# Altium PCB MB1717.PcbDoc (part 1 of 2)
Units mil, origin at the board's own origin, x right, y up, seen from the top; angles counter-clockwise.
Board outline 2760.94 x 3253.06 mil, 2 copper layers (Top Layer, Bottom Layer), stack 60.756 mil thick; 141 components, 128 nets, 519 pads, 417 vias.
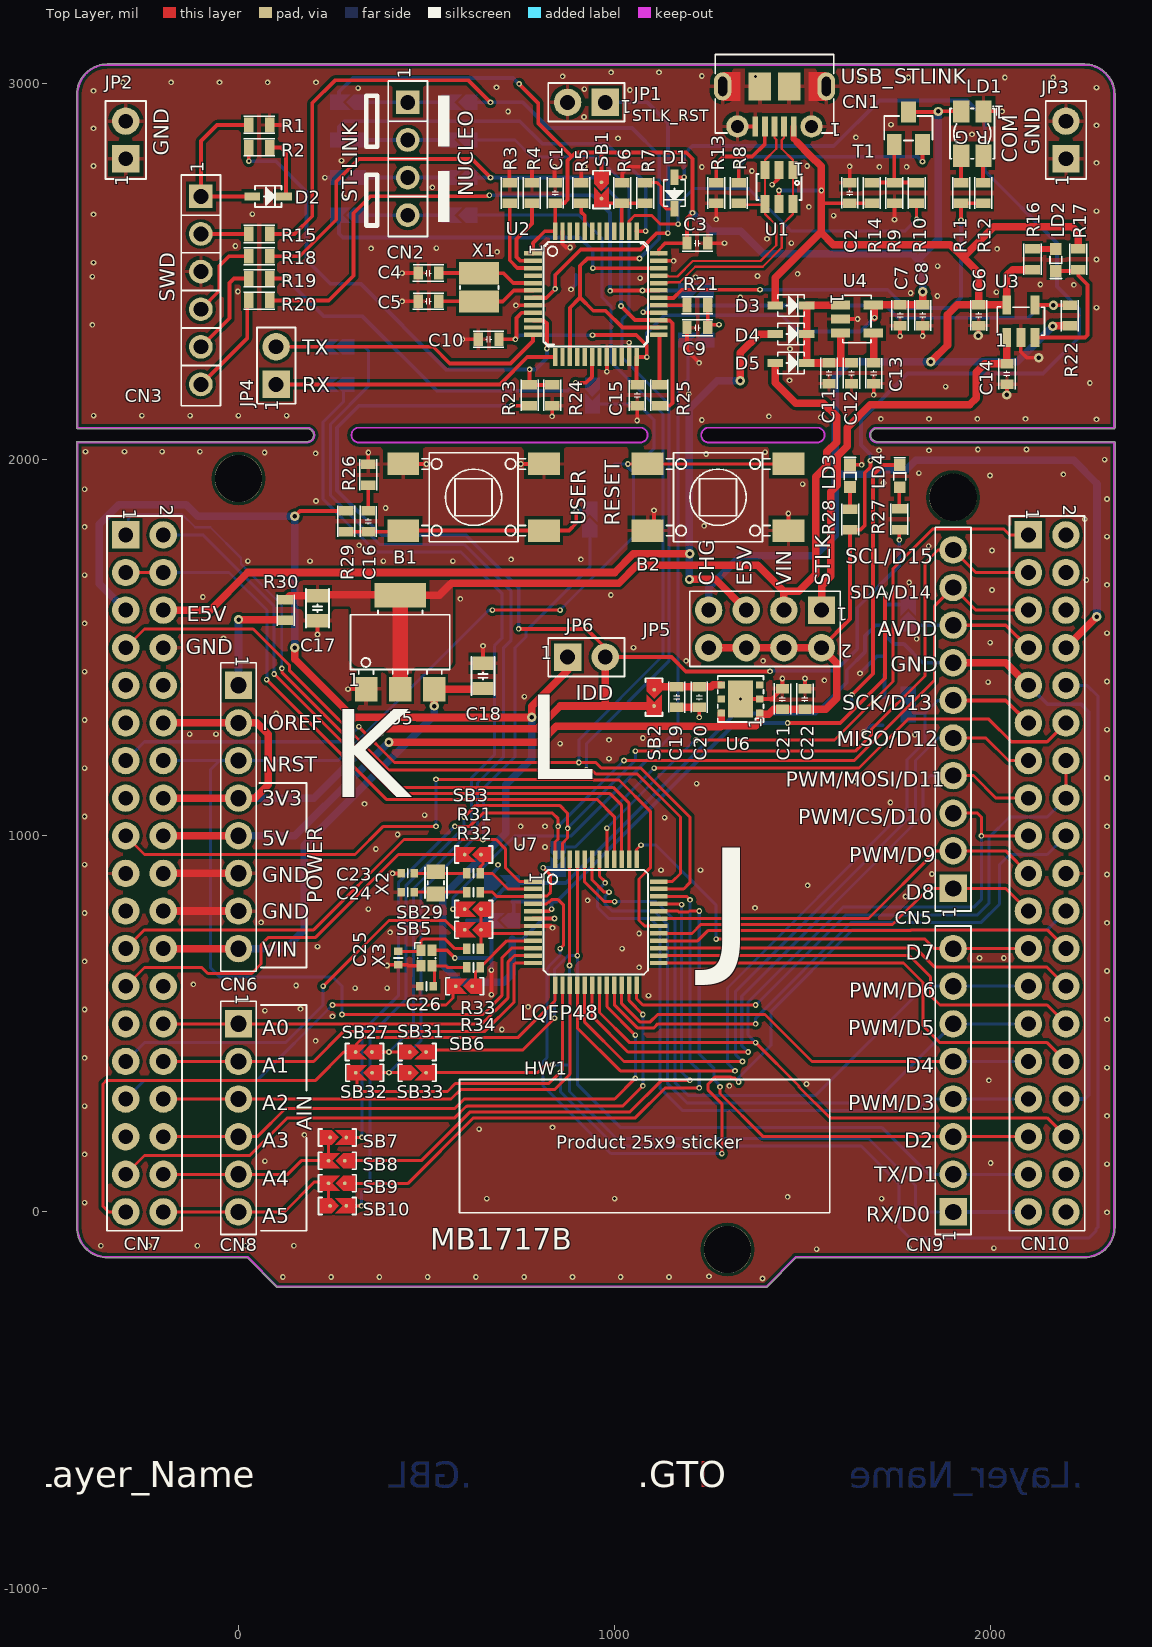
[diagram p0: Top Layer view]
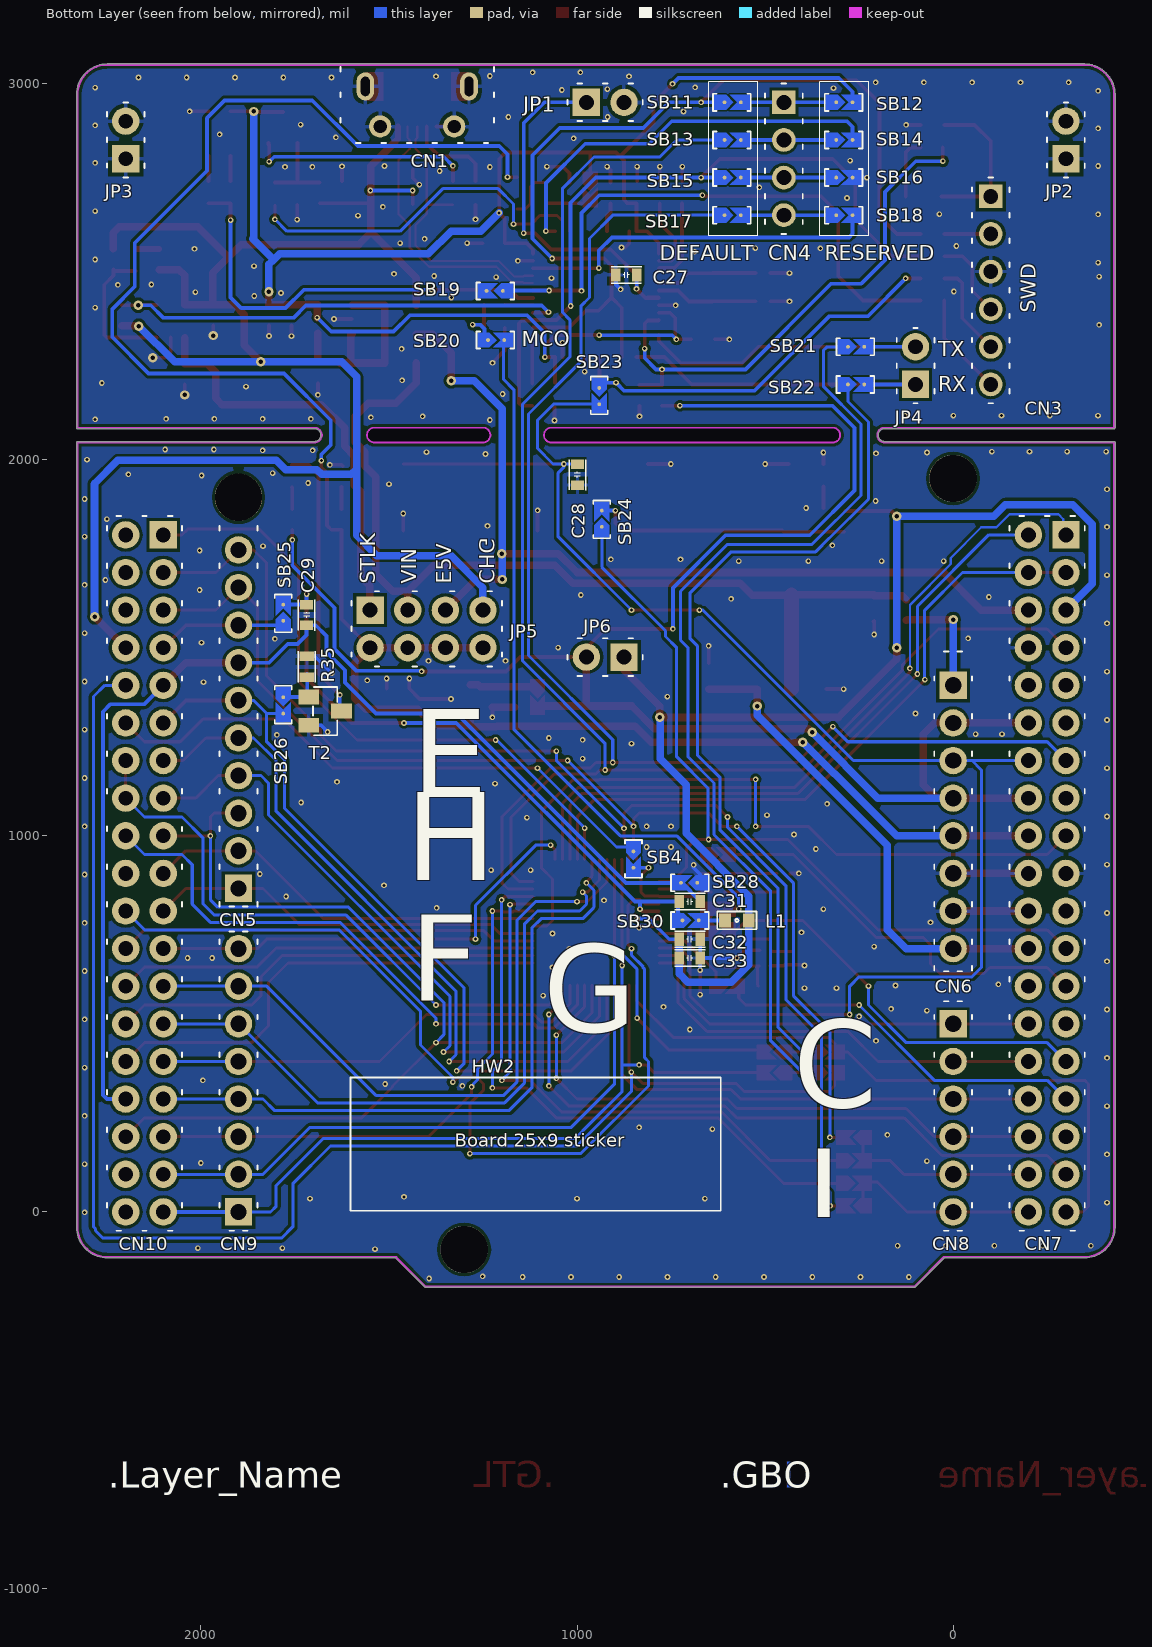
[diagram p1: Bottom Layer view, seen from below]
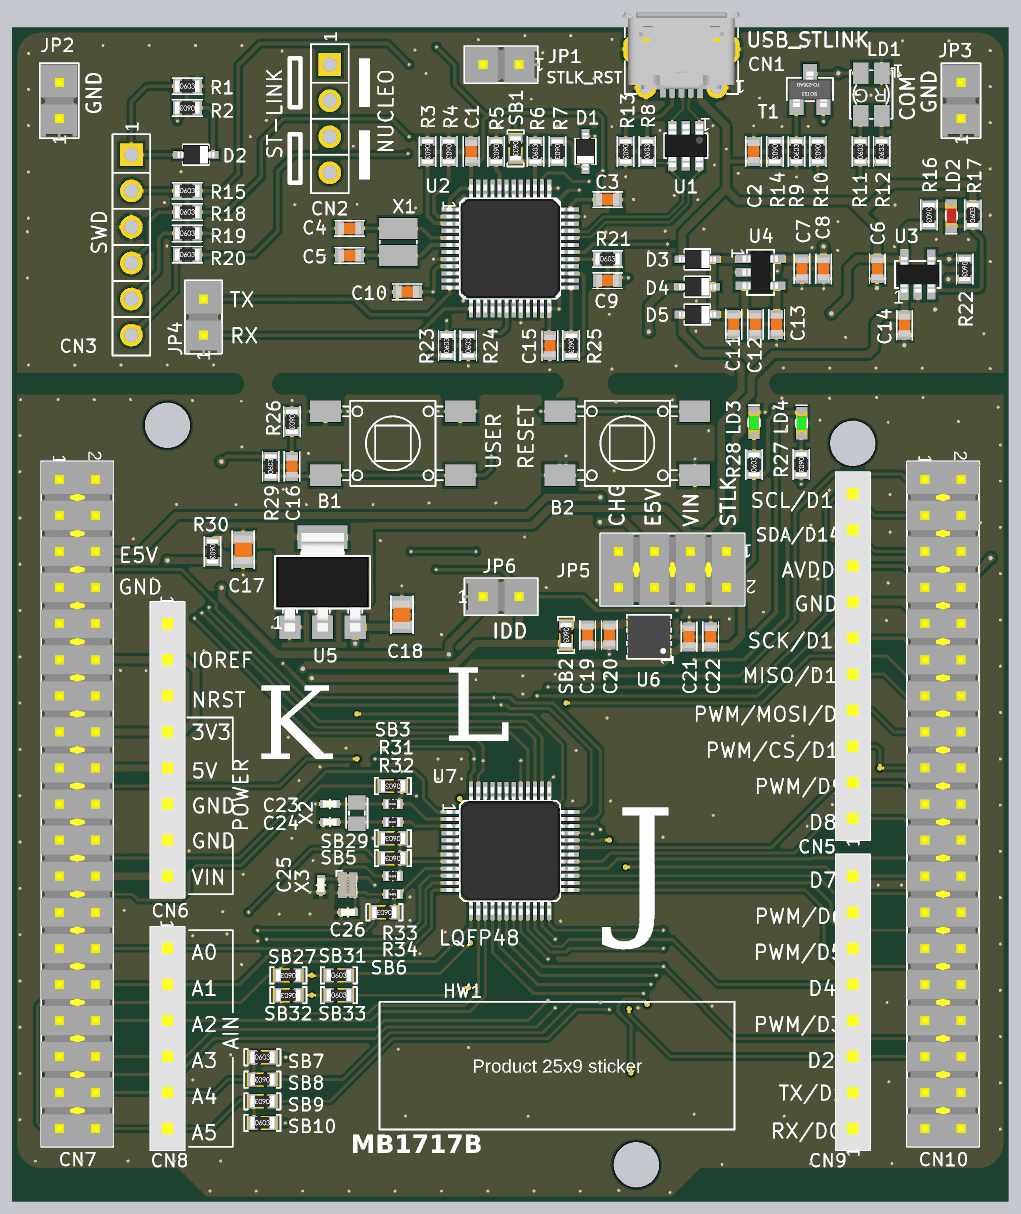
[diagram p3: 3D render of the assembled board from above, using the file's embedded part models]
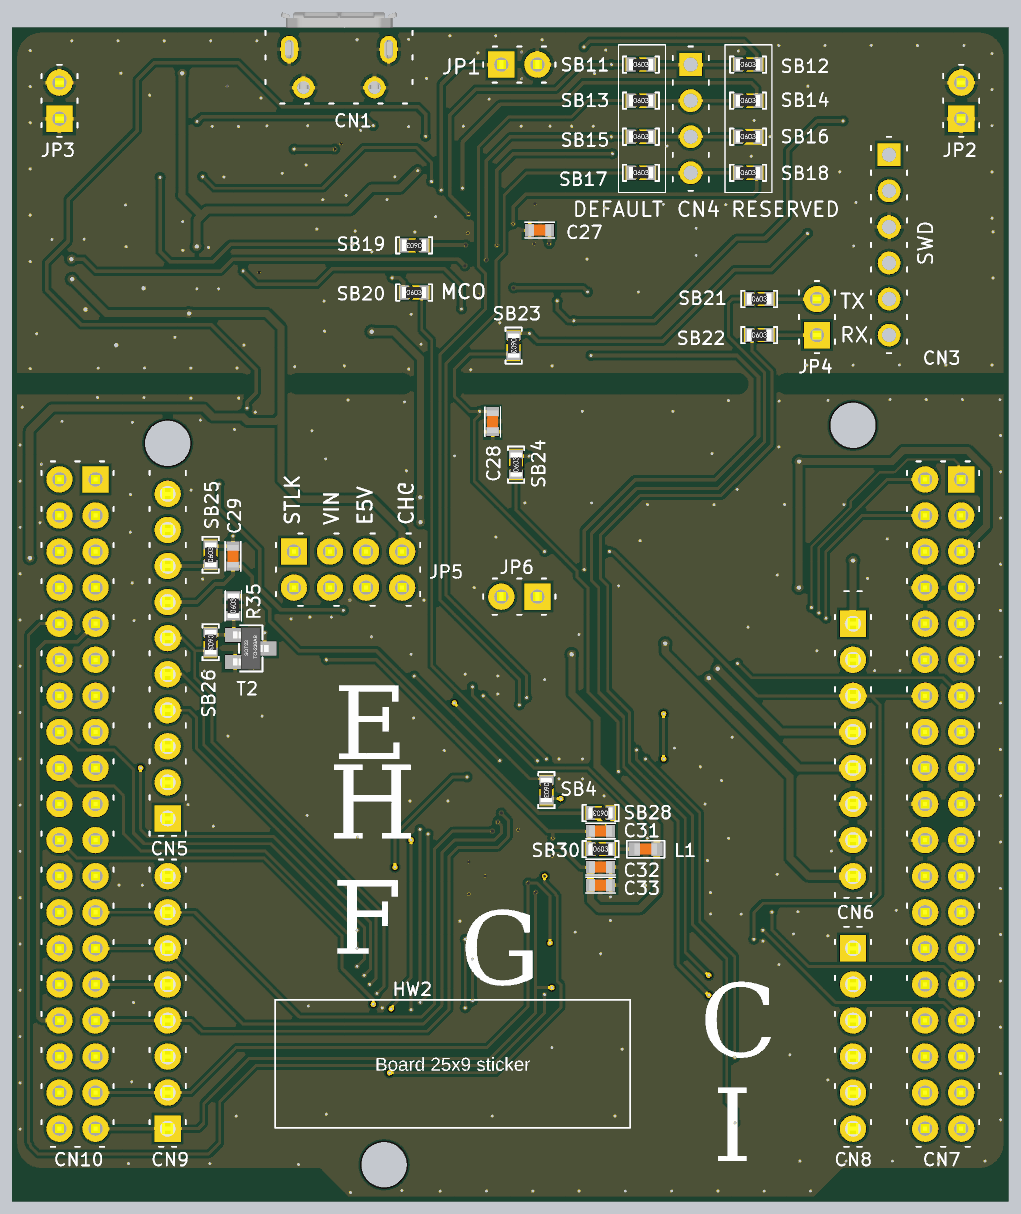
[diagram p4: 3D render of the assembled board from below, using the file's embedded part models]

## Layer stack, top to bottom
Top Solder: solder mask 0.591, Solder Resist, Dk 3.5
Top Layer: signal copper 1.378
Dielectric 1: core 58, FR-4, Dk 4.2
Bottom Layer: signal copper 1.378
Bottom Solder: solder mask 0.591, Solder Resist, Dk 3.5

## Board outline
-430.46,-40.95 ccw(c-349.21,-40.95) -349.21,-122.2 ccw(c-349.21,-119.69) -349.17,-122.2 23.77,-122.2 101.77,-200.2 ccw(c103.55,-198.43) 103.55,-200.94 1402.76,-200.94 ccw(c1402.76,-198.43) 1404.54,-200.2 1404.55,-200.19 cw(c1402.76,-198.43) 1404.53,-200.21 1482.54,-122.2 2249.22,-122.2 ccw(c2249.22,-40.95) 2330.47,-40.95 2330.47,2045.67 ccw(c2327.96,2045.67) 2327.96,2048.18 1698.04,2048.18 cw(c1698.04,2065.35) 1698.04,2082.52 2327.93,2082.52 ccw(c2327.96,2085.04) 2330.47,2085.04 2330.47,2970.87 ccw(c2249.22,2970.87) 2249.24,3052.12 ccw(c2249.22,3049.61) 2249.22,3052.12 -349.21,3052.12 ccw(c-349.21,3049.61) -349.23,3052.12 cw(c-349.21,2970.87) -349.21,3052.12 -349.23,3052.12 ccw(c-349.21,2970.87) -430.46,2970.87 -430.46,2085.04 ccw(c-427.95,2085.04) -427.92,2082.52 182.29,2082.52 cw(c182.29,2065.35) 199.46,2065.35 cw(c182.29,2065.35) 182.29,2048.18 -427.95,2048.18 ccw(c-427.95,2045.67) -430.46,2045.65
cut-out: 1250,2045.67 1538.59,2045.67 ccw(c1538.59,2065.35) 1538.59,2085.04 1250,2085.04 ccw(c1250,2065.35)
cut-out: 320.08,2045.67 1068.11,2045.67 ccw(c1068.11,2065.35) 1068.11,2085.04 320.08,2085.04 ccw(c320.08,2065.35)

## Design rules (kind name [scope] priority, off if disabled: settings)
Clearance U6 [(HasFootprint('ICC_DFN6-EPAD_3X3_P095'))] p1: gap=7 ignorepadtopadclearanceinfootprint=FALSE
Clearance X3 [(HasFootprint('CRY_NX1612SA_4P'))] p2: gap=5 ignorepadtopadclearanceinfootprint=FALSE
Clearance SB [(HasFootprint('SOLDER-BRIDGE_R0603-0R'))] p3: gap=5 ignorepadtopadclearanceinfootprint=FALSE except(0: Arc-Hole Track-Hole SMDPad-Hole THPad-Hole Via-Hole Fill-Hole Poly-Hole Region-Hole Text-Hole)
Clearance U2 [(ObjectKind = 'Pad') And (Component = 'U2') vs (ObjectKind = 'Pad') And (Component = 'U2')] p4: gap=7.8 ignorepadtopadclearanceinfootprint=FALSE except(0: Arc-Hole Track-Hole SMDPad-Hole THPad-Hole Via-Hole Fill-Hole Poly-Hole Region-Hole Text-Hole)
Clearance U7 [(ObjectKind = 'Pad') And (Component = 'U7') vs (ObjectKind = 'Pad') And (Component = 'U7')] p5: gap=7.8 ignorepadtopadclearanceinfootprint=FALSE except(0: Arc-Hole Track-Hole SMDPad-Hole THPad-Hole Via-Hole Fill-Hole Poly-Hole Region-Hole Text-Hole)
Clearance [All] p6: gap=8 ignorepadtopadclearanceinfootprint=FALSE except(0: Arc-Hole Track-Hole SMDPad-Hole THPad-Hole Via-Hole Fill-Hole Poly-Hole Region-Hole Text-Hole)
ComponentClearance [All] p1: gap=7.87 collisioncheckmode=3 verticalgap=7.87 showdistances=FALSE
DiffPairsRouting [All] p1: maxlimit=8.9 minlimit=8.9 mostfreqgap=8.9 toplayer_minwidth=15 toplayer_maxwidth=15 toplayer_prefwidth=15 bottomlayer_minwidth=15 bottomlayer_maxwidth=15 bottomlayer_prefwidth=15 maxuncoupledlength=500
HoleSize [All] p1: absolutevalues=TRUE maxlimit=150 minlimit=1 maxpercent=80.000 minpercent=20.000
MinimumSolderMaskSliver [All] p1: minsoldermaskwidth=0
PolygonConnect VIA [IsVia] p1: connectstyle=Direct reliefconductorwidth=10 reliefentries=4 polygonreliefangle="90 Angle" airgapwidth=10
PolygonConnect [All] p2: connectstyle=Relief reliefconductorwidth=10 reliefentries=4 polygonreliefangle="90 Angle" airgapwidth=10
RoutingVias [All] p1: holewidth=12 width=20 viastyle="Through Hole" minholewidth=8 minwidth=15 maxholewidth=28 maxwidth=50
SilkToSilkClearance [All] p1: silktosilkclearance=4
SilkToSolderMaskClearance [IsPad] p1: minsilkscreentomaskgap=0.5 clearancetoexposedcopper=TRUE
SolderMaskExpansion [All] p1: expansion=4 istentingtop=FALSE
Width [All] p1: maxlimit=40 minlimit=6 preferedwidth=10 minimp=50.000000 maximp=50.000000 favimp=50.000000
24 further rules are at their usual default settings.

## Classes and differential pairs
net class PF[0..3]: PF0 PF1 PF2 PF3
net class PD[0..3]: PD0 PD1 PD2 PD3
net class PC[6..15]: PC6 PC7 PC13 PC14 PC15
net class PB[0..15]: PB0 PB1 PB2 PB3 PB4 PB5 PB6 PB7 PB8 PB9 PB10 PB11 PB12 PB13 PB14 PB15
net class PA[0..15]: PA0 PA1 PA2 PA3 PA4 PA5 PA6 PA7 PA8 PA9 PA10 PA11 PA12 PA13 PA14 PA15
component class U_Arduino_Morpho_connectors: C29 CN5 CN6 CN7 CN8 CN9 CN10 LD4 R27 R30 R35 SB3 SB4 SB5 SB6 SB7 SB8 SB9 SB10 SB25 SB26 T2
component class ST_LINK_V2-1: C1 C2 C3 C4 C5 C6 C7 C8 C9 C10 C11 C12 C13 C14 C15 C27 CN1 CN2 CN3 D1 D2 D3 D4 D5 HW6 HW7 HW8 HW9 JP1 JP2 JP3 JP4 LD1 LD2 R1 R2 R3 R4 R5 R6 R7 R8 R9 R10 R11 R12 R13 R14 R15 R16 R17 R18 R19 R20 R21 R22 R23 R24 R25 SB1 SB11 SB12 SB13 SB14 SB15 SB16 SB17 SB18 SB19 SB20 SB21 SB22 SB23 T1 U1 U2 U3 U4 X1
component class Power: C17 C18 C19 C20 C21 C22 HW12 HW13 JP5 JP6 LD3 R28 SB2 U5 U6
component class MCU: B1 B2 C16 C23 C24 C25 C26 C28 C31 C32 C33 HW10 HW11 L1 R26 R29 R31 R32 R33 R34 SB24 SB27 SB28 SB29 SB30 SB31 SB32 SB33 U7 X2 X3
component class HW_Mechanical_Parts: HW1 HW2 HW4
differential pair STL_USB_D: +STL_USB_D_P -STL_USB_D_N

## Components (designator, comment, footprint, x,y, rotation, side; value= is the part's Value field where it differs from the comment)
B1 "SW-PUSH-CMS" SWI_WEALTHMETAL_TD-0341_4P_BLUE 625,1900 r270 top locked value=SWITCH
B2 "SW-PUSH-CMS" SWI_WEALTHMETAL_TD-0341_4P_BLACK 1275,1900 r90 top locked value=SWITCH
C1 "Capacitor" C0603 842,2709 r270 top value=100nF
C2 "Capacitor" C0603 1625,2709 r270 top value=100nF
C3 "Capacitor" C0603 1220,2575.68 r180 top value=100nF
C4 "Capacitor" C0603 505,2496 r0 top value=10pF
C5 "Capacitor" C0603 505,2421 r0 top value=10pF
C6 "Capacitor" C0603 1968,2384 r90 top value=1uF
C7 "Capacitor" C0603 1759.02,2383.94 r90 top value=1uF
C8 "Capacitor" C0603 1819.02,2383.94 r90 top value=100nF
C9 "Capacitor" C0603 1220,2351 r180 top value=20pF
C10 "Capacitor" C0603 665,2320 r0 top value=100nF
C11 "Capacitor" C0603 1569.87,2230 r90 top value=100nF
C12 "Capacitor" C0603 1629.87,2230 r90 top value=1uF
C13 "Capacitor" C0603 1688.87,2229.94 r90 top value=10nF
C14 "Capacitor" C0603 2043,2228 r90 top value=100nF
C15 "Capacitor" C0603 1060,2171 r90 top value=100nF
C16 "Capacitor" C0603 345,1836 r270 top value=100nF
C17 "Capacitor" C0805 210,1605 r90 top value=10uF
C18 "Capacitor" C0805 650,1425 r270 top value=10uF
C19 "Capacitor" C0603 1165,1368.69 r90 top value=100nF
C20 "Capacitor" C0603 1225,1368.69 r90 top value=1uF
C21 "Capacitor" C0603 1446,1363.69 r270 top value=100nF
C22 "Capacitor" C0603 1506,1363.69 r270 top value=1uF
C23 "Capacitor" C0402 450,900 r0 top value=8.2pF
C24 "Capacitor" C0402 450,850 r0 top value=8.2pF
C25 "Capacitor" C0402 425,675 r90 top value=4.3pF
C26 "Capacitor" C0402 500,600 r0 top value=4.3pF
C27 "Capacitor" C0603 869,2491 r0 bottom value=100nF
C28 "Capacitor" C0603 999,1959.97 r90 bottom value=100nF
C29 "Capacitor" C0603 1719,1587.06 r90 bottom value=100nF
C31 "Capacitor" C0603 700,825 r0 bottom value=100nF
C32 "Capacitor" C0603 700,725 r0 bottom value=100nF
C33 "Capacitor" C0603 700,675 r0 bottom value=4.7uF
CN1 "USB_uB_105017.0001" CON_USBMICROB_MOLEX_105017-0001_H2P90 1425,3049.39 r180 top locked value=USB_uB_105017-0001
CN2 "Header 4x1" CON_988-JIUBABA_PHFS25-11-04-G0B115-T-1 450,2800 r90 top
CN3 "Header 6x1" CON_988-JIUBABA_PHFS25-11-06-G0B115-T-1 -100,2450 r90 top locked value="Header 1x6"
CN5 "Socket 10x1" CON_SAMTEC_SSW-110-03-X-S 1900,1310 r90 top locked
CN6 "Socket 8x1" CON_SAMTEC_SSW-108-03-X-S 0,1050 r270 top locked
CN7 "Header 19x2" CON_SAMTEC_TSW-119-09-X-D -250,900 r270 top locked
CN8 "Socket 6x1" CON_SAMTEC_SSW-106-03-X-S 0,250 r270 top
CN9 "Socket 8x1" CON_SAMTEC_SSW-108-03-X-S 1900,350 r90 top locked
CN10 "Header 19x2" CON_SAMTEC_TSW-119-09-X-D 2150,900 r270 top locked
D1 "BAT60JFILM" DIO_SOD323 1159,2709 r270 top
D2 "BAT60JFILM" DIO_SOD323 79,2700 r0 top
D3 "BAT60JFILM" DIO_SOD323 1469,2410 r0 top locked
D4 "BAT60JFILM" DIO_SOD323 1469,2334 r0 top
D5 "BAT60JFILM" DIO_SOD323 1469,2257 r0 top
HW1 "STICKER_PRODUCT" STICKER_PRODUCT_25X9 1080,175 r0 top value="Sticker product"
HW2 "STICKER_BOARD" STICKER_BOARD_25X9 1110,180 r180 bottom value="Sticker board"
JP1 "Jumper_Header 2x1" CON_SAMTEC_TSW-102-07-G-S 925,2950 r180 top value="Shunt not fitted"
JP2 "Jumper_Header 2x1" CON_SAMTEC_TSW-102-09-X-S -300,2850 r90 top locked value="Header 2x1 16mm"
JP3 "Jumper_Header 2x1" CON_SAMTEC_TSW-102-09-X-S 2200,2850 r90 top locked value="Header 2x1 16mm"
JP4 "Jumper_Header 2x1" CON_SAMTEC_TSW-102-07-G-S 100,2250 r90 top locked value="Shunt not fitted"
JP5 "Jumper_Header 4x2 Fitted 1-2" CON_SAMTEC_TSW-104-07-X-D 1400,1550 r180 top value="Shunt Fitted 1-2"
JP6 "Jumper_Header 2x1 Fitted" CON_SAMTEC_TSW-102-07-G-S 925,1475 r0 top value="Shunt Fitted"
L1 "BEAD" L0603 575,775 r180 bottom value=600R@100MHz
LD1 "LD_BICOLOR_CMS" LED_BI-GR_HSMF-A201-A00J1 1951,2867 r180 top locked
LD2 "LED_red" LED_0603_RED 2173,2531 r270 top value=RED
LD3 "LED_green" LED_0603_GREEN 1626,1956.7 r90 top value=GREEN
LD4 "LED_green" LED_0603_GREEN 1758,1956 r90 top value=GREEN
R1 "Resistor" R0603 55,2890 r0 top value=10K
R2 "Resistor" R0603 55,2830 r180 top value=22R
R3 "Resistor" R0603 721,2709 r270 top value=10K
R4 "Resistor" R0603 780,2709 r270 top value=10K
R5 "Resistor" R0603 911,2709 r270 top value=100K
R6 "Resistor" R0603 1020,2709 r90 top value=4K7
R7 "Resistor" R0603 1081,2709 r270 top value=2K7
R8 "Resistor" R0603 1330,2709 r90 top value=1K5
R9 "Resistor" R0603 1744,2709 r90 top value=36K
R10 "Resistor" R0603 1803,2709 r270 top value=100R
R11 "Resistor" R0603 1921,2709 r90 top value=330R
R12 "Resistor" R0603 1980,2709 r90 top value=330R
R13 "Resistor" R0603 1270,2709 r270 top value=100K
R14 "Resistor" R0603 1684,2709 r270 top value=10K
R15 "Resistor" R0603 55,2600 r0 top value=22R
R16 "Resistor" R0603 2111,2533 r270 top value=1K
R17 "Resistor" R0603 2232.64,2533 r90 top value=47K
R18 "Resistor" R0603 55,2541 r0 top value=22R
R19 "Resistor" R0603 55,2482 r0 top value=22R
R20 "Resistor" R0603 55,2423 r0 top value=22R
R21 "Resistor" R0603 1220,2411 r0 top value=100R
R22 "Resistor" R0603 2210,2383 r270 top value=47K
R23 "Resistor" R0603 774,2171 r90 top value=4K7
R24 "Resistor" R0603 834,2171 r90 top value=4K7
R25 "Resistor" R0603 1119,2171 r270 top value=100R
R26 "Resistor" R0603 345,1960 r270 top value=100R
R27 "Resistor" R0603 1757,1841.3 r270 top value=510R
R28 "Resistor" R0603 1626,1841 r90 top value=1K
R29 "Resistor" R0603 286,1836 r90 top value=4K7
R30 "Resistor" R0603 125,1600 r270 top value=1K
R31 "Resistor" R0402 625,900 r0 top value=0R
R32 "Resistor" R0402 625,850 r0 top value=0R
R33 "Resistor" R0402 625,700 r0 top value=0R
R34 "Resistor" R0402 625,650 r0 top value=0R
R35 "Resistor" R0603 1718,1449.62 r90 bottom value=1M
SB1 "SB_OFF" SOLDER-BRIDGE_R0603-0R 965,2717.72 r270 top
SB2 "SB_ON" SOLDER-BRIDGE_R0603-0R 1105,1368.69 r270 top
SB3 "SB_OFF" SOLDER-BRIDGE_R0603-0R 625,950 r180 top
SB4 "SB_OFF" SOLDER-BRIDGE_R0603-0R 850,938.62 r270 bottom
SB5 "SB_ON" SOLDER-BRIDGE_R0603-0R 625,750 r180 top
SB6 "SB_ON" SOLDER-BRIDGE_R0603-0R 601.38,600 r180 top
SB7 "SB_OFF" SOLDER-BRIDGE_R0603-0R 263,198 r0 top
SB8 "SB_ON" SOLDER-BRIDGE_R0603-0R 263,136 r180 top
SB9 "SB_ON" SOLDER-BRIDGE_R0603-0R 263,76 r180 top
SB10 "SB_OFF" SOLDER-BRIDGE_R0603-0R 263,16 r0 top
SB11 "SB_ON" SOLDER-BRIDGE_R0603-0R 588,2950 r180 bottom
SB12 "SB_OFF" SOLDER-BRIDGE_R0603-0R 291,2950 r180 bottom
SB13 "SB_ON" SOLDER-BRIDGE_R0603-0R 588,2850 r180 bottom
SB14 "SB_OFF" SOLDER-BRIDGE_R0603-0R 291,2850 r180 bottom locked
SB15 "SB_ON" SOLDER-BRIDGE_R0603-0R 588,2750 r180 bottom
SB16 "SB_OFF" SOLDER-BRIDGE_R0603-0R 291,2750 r180 bottom locked
SB17 "SB_ON" SOLDER-BRIDGE_R0603-0R 588,2650 r180 bottom
SB18 "SB_OFF" SOLDER-BRIDGE_R0603-0R 291,2650 r180 bottom
SB19 "SB_ON" SOLDER-BRIDGE_R0603-0R 1216.85,2448.76 r0 bottom
SB20 "SB_OFF" SOLDER-BRIDGE_R0603-0R 1217,2318 r180 bottom
SB21 "SB_ON" SOLDER-BRIDGE_R0603-0R 260,2300 r180 bottom
SB22 "SB_ON" SOLDER-BRIDGE_R0603-0R 260,2200 r180 bottom
SB23 "SB_ON" SOLDER-BRIDGE_R0603-0R 941,2171 r270 bottom
SB24 "SB_ON" SOLDER-BRIDGE_R0603-0R 934.11,1841 r90 bottom
SB25 "SB_OFF" SOLDER-BRIDGE_R0603-0R 1781,1591.06 r90 bottom
SB26 "SB_ON" SOLDER-BRIDGE_R0603-0R 1781,1348.62 r270 bottom
SB27 "SB_ON" SOLDER-BRIDGE_R0603-0R 335,425 r180 top
SB28 "SB_ON" SOLDER-BRIDGE_R0603-0R 700,875 r0 bottom
SB29 "SB_OFF" SOLDER-BRIDGE_R0603-0R 625,805 r180 top
SB30 "SB_ON" SOLDER-BRIDGE_R0603-0R 700,775 r180 bottom
SB31 "SB_OFF" SOLDER-BRIDGE_R0603-0R 475,425 r0 top
SB32 "SB_ON" SOLDER-BRIDGE_R0603-0R 335.32,370 r180 top
SB33 "SB_OFF" SOLDER-BRIDGE_R0603-0R 475,370 r0 top
T1 "9013-SOT23" NPN_SOT23 1781,2881 r0 top locked value="NPN SOT23"
T2 "BSN20" MOS_SOT23 1669.69,1331.4 r270 bottom value=BSN20BK
U1 "USBLC6-2SC6" ESD_SOT23-6L 1437,2725 r180 top locked
U2 "STM32F103CBT6" ICC_LQFP48_7X7_P050 950,2440 r270 top locked
U3 "STMPS2141STR" MOS_SOT23-5L 2080,2368 r0 top
U4 "LDK120M33R" REG_SOT23-5L 1644,2374 r270 top locked
U5 "LD1117S50TR" REG_SOT223-TAB 430,1515 r0 top locked
U6 "LDL112PV33R" ICC_DFN6-EPAD_3X3_P095 1335,1363.69 r90 top
U7 "STM32C031C6T6" ICC_LQFP48_7X7_P050 950,770 r270 top locked
X1 "XTAL_2_PINS" CRY_NX3225GD_2P 640,2458 r90 top value="NX3225GD 8MHz"
X2 "XTAL_2_PINS" CRY_NX2012SA_2P 525,875 r90 top value="NX2012SA 32.768KHz"
X3 "XTAL_4_PINS" CRY_NX1612SA_4P 500,675 r270 top value=NX1612SA_48MHz

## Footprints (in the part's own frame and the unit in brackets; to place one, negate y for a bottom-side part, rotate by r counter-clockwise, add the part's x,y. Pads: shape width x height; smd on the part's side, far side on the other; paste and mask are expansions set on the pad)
C0402 [mm]
  rect 0.51x0.56 smd mask+0.05: 1(-0.45,0) 2(0.45,0)
  silkscreen extent 0,-0.3 0,0.3, body extent -0.5,-0.3 0.5,0.3, height 0.4
C0603 [mm]
  rect 0.64x0.89 smd mask+0.05: 1(-0.7,0) 2(0.7,0)
  silkscreen extent -1.05,-0.55 1.02,0.55, body extent -0.9,-0.5 0.9,0.5, height 1.4
C0805 [mm]
  rect 0.9x1.4 smd mask+0.05: 1(-0.85,0) 2(0.85,0)
  silkscreen extent -1.3,-0.77 1.3,0.77, body extent -1.1,-0.7 1.1,0.7, height 1.35
CON_988-JIUBABA_PHFS25-11-04-G0B115-T-1 [mm]
  rect 1.6x1.6 hole 1 mask+0.05: 1(3.81,0)
  round 1.6 hole 1 mask+0.05: 2(1.27,0) 3(-1.27,0) 4(-3.81,0)
  silkscreen extent -5.25,-1.33 5.25,1.33, body extent -5.25,-1.33 5.25,1.33, height 8.85
CON_988-JIUBABA_PHFS25-11-06-G0B115-T-1 [mm]
  rect 1.6x1.6 hole 1 mask+0.05: 1(6.35,0)
  round 1.6 hole 1 mask+0.05: 2(3.81,0) 3(1.27,0) 4(-1.27,0) 5(-3.81,0) 6(-6.35,0)
  silkscreen extent -7.79,-1.33 7.79,1.33, body extent -7.79,-1.33 7.79,1.33, height 8.85
CON_SAMTEC_SSW-106-03-X-S [mm]
  rect 1.85x1.85 / inner round 1.85 / far side rect 1.85x1.85 hole 1.1 mask+0.05: 1(-6.35,0)
  round 1.85 hole 1.1 mask+0.05: 2(-3.81,0) 3(-1.27,0) 4(1.27,0) 5(3.81,0) 6(6.35,0)
  silkscreen extent -7.88,-1.2 7.88,1.2, body extent -7.88,-1.21 7.88,1.21, height 8.51
CON_SAMTEC_SSW-108-03-X-S [mm]
  rect 1.85x1.85 / inner round 1.85 / far side rect 1.85x1.85 hole 1.1 mask+0.05: 1(-8.89,0)
  round 1.85 hole 1.1 mask+0.05: 2(-6.35,0) 3(-3.81,0) 4(-1.27,0) 5(1.27,0) 6(3.81,0) 7(6.35,0) 8(8.89,0)
  silkscreen extent -10.42,-1.2 10.42,1.2, body extent -10.42,-1.21 10.42,1.21, height 8.51
CON_SAMTEC_SSW-110-03-X-S [mm]
  rect 1.85x1.85 / inner round 1.85 / far side rect 1.85x1.85 hole 1.1 mask+0.05: 1(-11.43,0)
  round 1.85 hole 1.1 mask+0.05: 2(-8.89,0) 3(-6.35,0) 4(-3.81,0) 5(-1.27,0) 6(1.27,0) 7(3.81,0) 8(6.35,0) 9(8.89,0) 10(11.43,0)
  silkscreen extent -12.96,-1.2 12.96,1.2, body extent -12.96,-1.21 12.96,1.21, height 8.51
CON_SAMTEC_TSW-102-07-G-S [mm]
  rect 1.85x1.85 / inner round 1.85 / far side rect 1.85x1.85 hole 1 mask+0.05: 1(-1.27,0)
  round 1.85 hole 1 mask+0.05: 2(1.27,0)
  silkscreen extent -2.58,-1.3 2.58,1.3, body extent -2.67,-1.3 2.58,1.3, height 8.38
CON_SAMTEC_TSW-102-09-X-S [mm]
  rect 1.85x1.85 / inner round 1.85 / far side rect 1.85x1.85 hole 1 mask+0.05: 1(-1.27,0)
  round 1.85 hole 1 mask+0.05: 2(1.27,0)
  silkscreen extent -2.64,-1.37 2.64,1.37, body extent -2.67,-1.3 2.58,1.3, height 8.38
CON_SAMTEC_TSW-104-07-X-D [mm]
  rect 1.85x1.85 / inner round 1.85 / far side rect 1.85x1.85 hole 1 mask+0.05: 1(-3.81,-1.27)
  round 1.85 hole 1 mask+0.05: 2(-3.81,1.27) 3(-1.27,-1.27) 4(-1.27,1.27) 5(1.27,-1.27) 6(1.27,1.27) 7(3.81,-1.27) 8(3.81,1.27)
  silkscreen extent -5.08,-2.54 5.08,2.54, body extent -5.08,-2.54 5.08,2.54, height 8.38
CON_SAMTEC_TSW-119-09-X-D [mm]
  rect 1.85x1.85 / inner round 1.85 / far side rect 1.85x1.85 hole 1 mask+0.05: 1(-22.86,-1.27)
  round 1.85 hole 1 mask+0.05: 2(-22.86,1.27) 3(-20.32,-1.27) 4(-20.32,1.27) 5(-17.78,-1.27) 6(-17.78,1.27) 7(-15.24,-1.27) 8(-15.24,1.27) 9(-12.7,-1.27) 10(-12.7,1.27) 11(-10.16,-1.27) 12(-10.16,1.27) 13(-7.62,-1.27) 14(-7.62,1.27) 15(-5.08,-1.27) 16(-5.08,1.27) 17(-2.54,-1.27) 18(-2.54,1.27) 19(0,-1.27) 20(0,1.27) 21(2.54,-1.27) 22(2.54,1.27) 23(5.08,-1.27) 24(5.08,1.27) 25(7.62,-1.27) 26(7.62,1.27) 27(10.16,-1.27) 28(10.16,1.27) 29(12.7,-1.27) 30(12.7,1.27) 31(15.24,-1.27) 32(15.24,1.27) 33(17.78,-1.27) 34(17.78,1.27) 35(20.32,-1.27) 36(20.32,1.27) 37(22.86,-1.27) 38(22.86,1.27)
  silkscreen extent -24.13,-2.54 24.13,2.54, body extent -24.13,-2.55 24.13,2.54, height 8.38
CON_USBMICROB_MOLEX_105017-0001_H2P90 [mm]
  rect 0.4x1.35 smd mask+0.05: 1(-1.3,4.15) 2(-0.65,4.15) 3(0,4.15) 4(0.65,4.15) 5(1.3,4.15)
  round 1.5 hole 0.9 mask+0.05: 6(-2.5,4.15) 7(2.5,4.15)
  oval 1.2x1.9 hole 0.6 slot 1.3 at 90 deg mask+0.05: 8(3.5,1.45) 9(-3.5,1.45)
  rect 1.5x1.9 smd mask+0.05: 10(-1,1.45) 11(1,1.45)
  Top Layer region: -3.5,2.4 -2.3,2.4 -2.3,0.5 -3.5,0.5 -3.5,2.4
  Top Layer region: 2.3,2.4 3.5,2.4 3.5,0.5 2.3,0.5 2.3,2.4
  silkscreen extent -4,-0.7 4,4.6, body extent -4.1,-1.15 4.1,4.66, height 2.9
CRY_NX1612SA_4P [mm] "MCD-02262"
  rect 0.75x0.6 smd mask+0.038: 1(-0.525,-0.375) 2(0.525,-0.375) 3(0.525,0.375) 4(-0.525,0.375)
  silkscreen extent -1.02,-0.8 0.03,0.6, body extent -0.8,-0.6 0.8,0.6, height 0.51
CRY_NX2012SA_2P [mm]
  rect 1x1.25 smd mask+0.05: 1(-0.75,0) 2(0.75,0)
  silkscreen extent -1.05,-0.75 1.05,0.75, body extent -1.05,-0.63 1.05,0.63, height 0.6
CRY_NX3225GD_2P [mm]
  rect 1.5x2.7 smd mask+0.05: 1(-0.95,0) 2(0.95,0)
  silkscreen extent -0.1,-1.3 0.1,1.3, body extent -1.65,-1.3 1.65,1.3, height 1
DIO_SOD323 [mm]
  rect 1.06x0.54 smd mask+0.05: 1(-1.07,0) 2(1.07,0)
  silkscreen extent -0.9,-0.72 0.9,0.72, body extent -1.3,-0.78 1.3,0.78, height 1.17
ESD_SOT23-6L [mm]
  rect 0.6x1.2 smd mask+0.05: 1(-0.95,-1.15) 2(0,-1.15) 3(0.95,-1.15) 4(0.95,1.15) 5(0,1.15) 6(-0.95,1.15)
  silkscreen extent -1.53,-0.87 1.53,0.87, body extent -1.52,-1.5 1.52,1.5, height 1.45
ICC_DFN6-EPAD_3X3_P095 [mm]
  rect 0.45x0.5 smd mask+0.05: 1(-0.95,-1.3) 2(0,-1.3) 3(0.95,-1.3) 4(0.95,1.3) 5(0,1.3) 6(-0.95,1.3)
  rect 2.5x1.7 smd mask+0.05: EP(0,0)
  silkscreen extent -1.55,-1.55 1.55,1.55, body extent -1.55,-1.55 1.55,1.55, height 1
ICC_LQFP48_7X7_P050 [mm]
  rect 0.3x1.2 smd mask+0.05: 1(-2.75,-4.25) 2(-2.25,-4.25) 3(-1.75,-4.25) 4(-1.25,-4.25) 5(-0.75,-4.25) 6(-0.25,-4.25) 7(0.25,-4.25) 8(0.75,-4.25) 9(1.25,-4.25) 10(1.75,-4.25) 11(2.25,-4.25) 12(2.75,-4.25) 25(2.75,4.25) 26(2.25,4.25) 27(1.75,4.25) 28(1.25,4.25) 29(0.75,4.25) 30(0.25,4.25) 31(-0.25,4.25) 32(-0.75,4.25) 33(-1.25,4.25) 34(-1.75,4.25) 35(-2.25,4.25) 36(-2.75,4.25)
  rect 1.2x0.3 smd mask+0.05: 13(4.25,-2.75) 14(4.25,-2.25) 15(4.25,-1.75) 16(4.25,-1.25) 17(4.25,-0.75) 18(4.25,-0.25) 19(4.25,0.25) 20(4.25,0.75) 21(4.25,1.25) 22(4.25,1.75) 23(4.25,2.25) 24(4.25,2.75) 37(-4.25,2.75) 38(-4.25,2.25) 39(-4.25,1.75) 40(-4.25,1.25) 41(-4.25,0.75) 42(-4.25,0.25) 43(-4.25,-0.25) 44(-4.25,-0.75) 45(-4.25,-1.25) 46(-4.25,-1.75) 47(-4.25,-2.25) 48(-4.25,-2.75)
  silkscreen extent -3.52,-3.52 3.52,3.52, body extent -4.5,-4.5 4.5,4.5, height 1.6
L0603 [mm]
  rect 0.8x0.95 smd mask+0.05: 1(-0.8,0) 2(0.8,0)
  silkscreen extent -1.33,-0.6 1.33,0.6, body extent -0.87,-0.47 0.87,0.47, height 0.95
LED_0603_GREEN [mm]
  rect 0.8x0.8 smd mask+0.05: 1(-0.75,0) 2(0.75,0)
  silkscreen extent -0.25,-0.4 1.25,0.4, body extent -0.8,-0.4 0.8,0.4, height 0.6
LED_0603_RED [mm]
  rect 0.8x0.8 smd mask+0.05: 1(-0.75,0) 2(0.75,0)
  silkscreen extent -0.25,-0.4 1.25,0.4, body extent -0.8,-0.4 0.8,0.4, height 0.6
LED_BI-GR_HSMF-A201-A00J1 [mm] "MCD-00051"
  rect 1.1x1.5 smd mask+0.05: 1(-0.75,-1.5) 2(-0.75,1.5) 3(0.75,1.5) 4(0.75,-1.5)
  silkscreen extent -1.65,-1.85 1.5,1.7, body extent -1.5,-1.85 1.5,1.85, height 2.1
MOS_SOT23 [mm]
  rect 1x1.4 smd mask+0.05: 1(-0.95,-1.1) 2(0.95,-1.1) 3(0,1.1)
  silkscreen extent -1.63,-0.82 1.63,0.82, body extent -1.56,-1.25 1.56,1.25, height 1.1
MOS_SOT23-5L [mm]
  rect 0.6x1.3 smd mask+0.05: 1(-0.95,-1.1) 2(0,-1.1) 3(0.95,-1.1) 4(0.95,1.1) 5(-0.95,1.1)
  silkscreen extent -1.6,-0.95 1.6,0.97, body extent -1.52,-1.25 1.52,1.25, height 1.45
NPN_SOT23 [mm]
  rect 1x1.4 smd mask+0.05: 1(-0.95,-1.1) 2(0.95,-1.1) 3(0,1.1)
  silkscreen extent -1.63,-0.82 1.63,0.82, body extent -1.56,-1.25 1.56,1.25, height 1.1
R0402 [mm]
  rect 0.51x0.7 smd mask+0.05: 1(-0.45,0) 2(0.45,0)
  silkscreen extent 0,-0.3 0,0.3, body extent -0.52,-0.3 0.52,0.3, height 0.4
R0603 [mm]
  rect 0.64x1 smd mask+0.05: 1(-0.7,0) 2(0.7,0)
  silkscreen extent -1.05,-0.58 1.05,0.58, body extent -0.9,-0.5 0.9,0.5, height 0.56
REG_SOT23-5L [mm]
  rect 0.6x1.3 smd mask+0.05: 1(-0.95,-1.1) 2(0,-1.1) 3(0.95,-1.1) 4(0.95,1.1) 5(-0.95,1.1)
  silkscreen extent -1.6,-0.95 1.6,0.97, body extent -1.52,-1.25 1.52,1.25, height 1.1
REG_SOT223-TAB [mm]
  rect 1.5x1.65 smd mask+0.05: 1(-2.3,-3.175) 2(0,-3.175) 3(2.3,-3.175)
  rect 3.5x1.65 smd mask+0.05: 4(0,3.175)
  silkscreen extent -3.35,-2.15 3.35,2.12, body extent -3.35,-3.48 3.35,3.48, height 1.8
SOLDER-BRIDGE_R0603-0R [mil]
  round 10 smd paste-393.7: 1(-19.68,0) 2(23.62,0)
  Top Layer region: -5.91,19.68 13.78,0 -5.91,-19.68 47.24,-19.68 47.24,19.68 -5.91,19.68
  Top Layer region: -47.24,-19.68 -47.24,19.68 -15.75,19.68 3.94,0 -15.75,-19.68 -47.24,-19.68
  silkscreen extent -50,-23 50,23, body extent -36,-20 36,20, height 22
STICKER_BOARD_25X9 [mil] "Sticker to mention board CPN code"
  silkscreen extent -492,-177 492,177
STICKER_PRODUCT_25X9 [mil] "Sticker to mention board CPN code"
  silkscreen extent -492,-177 492,177
SWI_WEALTHMETAL_TD-0341_4P_BLACK [mm]
  rect 1.52x2.16 smd mask+0.05: 1(-2.25,-4.75) 2(-2.25,4.75) 3(2.25,-4.75) 4(2.25,4.75)
  silkscreen extent -3,-3.5 3,3.5, body extent -3,-5.15 3,5.15, height 7.55
SWI_WEALTHMETAL_TD-0341_4P_BLUE [mm]
  rect 1.52x2.16 smd mask+0.05: 1(-2.25,-4.75) 2(-2.25,4.75) 3(2.25,-4.75) 4(2.25,4.75)
  silkscreen extent -3,-3.5 3,3.5, body extent -3,-5.15 3,5.15, height 7.55

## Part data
B1: library part MCD-00002, "Non-Open Push-Button 0.1A 24V", Manufacturer=WEALTHMETAL, Manufacturer_Part_Number=TD-0341
B2: library part MCD-00001, "Non-Open Push-Button 0.1A 24V BLACK", Manufacturer=WEALTHMETAL, Manufacturer_Part_Number=TD-0341
C1 C2 C3 C8 C10 C11 C14 C15 C16 C19 C21 C27 C28 C29 C31 C32: library part MCD-00211, "Capacitor, MLCC, 100nF, 16V, X7R, +/-10%, 0603, T=0,8mm", Alternate_Manufacturer=MURATA, Alternate_Manufacturer_Part_Number=GCM155R71C104KA55D, Manufacturer=YAGEO, Manufacturer_Part_Number=CC0603KRX7R7BB104, Package=C0603
C4 C5: library part MCD-00637, "Capacitor, MLCC, 10pF, 50V, NPO, +/-5%, 0603, T=0,8mm", Alternate_Manufacturer=MURATA, Alternate_Manufacturer_Part_Number=GCM155R71C104KA55D, Manufacturer=YAGEO, Manufacturer_Part_Number=CC0603JRNPO9BN100, Package=C0603
C6 C7 C12 C20 C22: library part MCD-00010, "Capacitor, MLCC, 1uF, 16V, X5R, +/-10%, 0603, T=0,8mm", Alternate_Manufacturer=MURATA, Alternate_Manufacturer_Part_Number=GCM155R71C104KA55D, Manufacturer=YAGEO, Manufacturer_Part_Number=CC0603KRX5R7BB105, Package=C0603
C9: library part MCD-00638, "Capacitor, MLCC, 20pF, 50V, NPO, +/-5%, 0603, T=0,8mm", Alternate_Manufacturer=MURATA, Alternate_Manufacturer_Part_Number=GCM155R71C104KA55D, Manufacturer=YAGEO, Manufacturer_Part_Number=CC0603JRNPO9BN200, Package=C0603
C13: library part MCD-00017, "Capacitor, MLCC, 10nF, 50V, X7R, +/-10%, 0603, T=0.8mm", Alternate_Manufacturer=MURATA, Alternate_Manufacturer_Part_Number=GCM155R71C104KA55D, Manufacturer=YAGEO, Manufacturer_Part_Number=CC0603KRX7R9BB103, Package=C0603
C17 C18: library part MCD-00014, "Capacitor, MLCC, 10uF, 25V, X5R, +/-10%, 0805, T=0,85mm", Alternate_Manufacturer=MURATA, Alternate_Manufacturer_Part_Number=GCM155R71C104KA55D, Manufacturer=YAGEO, Manufacturer_Part_Number=CC0805KRX5R8BB106, Package=C0805
C23 C24: library part MCD-01932, "Capacitor, MLCC, 8.2pF, 50V, NPO, +/- 0.25pF, 0402, T=0,5mm", Alternate_Manufacturer=N/A, Manufacturer=YAGEO, Manufacturer_Part_Number=CC0402CRNPO9BN8R2, Package=C0402
C25 C26: library part MCD-01706, "Capacitor, MLCC, 4.3pF, 50V, NPO, +/-0.25pF, 0402, T=0,5mm", Alternate_Manufacturer=MURATA, Alternate_Manufacturer_Part_Number=GCM155R71C104KA55D, Manufacturer=YAGEO, Manufacturer_Part_Number=CC0402CRNPO9BN4R3, Package=C0402
C33: library part MCD-00009, "Capacitor, MLCC, 4.7uF, 16V, X5R, +/-10%, 0603, T=0.8mm", Alternate_Manufacturer=MURATA, Alternate_Manufacturer_Part_Number=GCM155R71C104KA55D, Manufacturer=YAGEO, Manufacturer_Part_Number=CC0603KRX5R7BB475, Package=C0603
CN1: library part MCD-00028, "USB-MICRO-B, 0.65mm, RA, SMT, Bottom Mount,", Manufacturer=MOLEX, Manufacturer_Part_Number=1050170001
CN2: library part MCD-00313, "Header, 4x1, 2.54mm, VR, TH, Height 6mm/3mm", Alternate_Manufacturer=LIANYI, Alternate_Manufacturer_Part_Number=313104S1411160, Manufacturer=JIUBABA, Manufacturer_Part_Number=PHFS25-11-04-G0B115-T-1
CN3: library part MCD-00316, "Header, 6x1, 2.54mm, VR, TH, Height 6mm/3mm", Alternate_Manufacturer=LIANYI, Alternate_Manufacturer_Part_Number=313106S1411160, Manufacturer=JIUBABA, Manufacturer_Part_Number=PHFS25-11-06-G0B115-T-1
CN5: library part MCD-00262, "Socket, 10x1, 2.54mm, VR, TH, Height 8.51mm/10mm", Manufacturer=SAMTEC, Manufacturer_Part_Number=SSW-110-03-G-S
CN6 CN9: library part MCD-00261, "Socket, 8x1, 2.54mm, VR, TH, Height 8.51mm/10mm", Manufacturer=SAMTEC, Manufacturer_Part_Number=SSW-108-03-G-S
CN7 CN10: library part MCD-00213, "Header, 19x2, 2,54mm, VR, TH, Height 5.84mm/10.16mm", Manufacturer=SAMTEC, Manufacturer_Part_Number=TSW-119-09-G-D
CN8: library part MCD-00260, "Socket, 6x1, 2.54mm, VR, TH, Height 8.51mm/10mm", Manufacturer=SAMTEC, Manufacturer_Part_Number=SSW-106-03-G-S
D1 D2 D3 D4 D5: library part MCD-00034, Manufacturer=STMICROELECTRONICS
HW1: library part MCD-00547, "Sticker product 25x9 mm", Alternate_Manufacturer=N/A
HW2: library part MCD-00235, "Sticker Board 25x9 mm", Alternate_Manufacturer=N/A
JP1 JP4: library part MCD-00045, "Header, 2x1, 2,54mm, VR, TH, Height 5.84mm/2.54mm", Alternate_Manufacturer="JIUBABA; LIANYI", Alternate_Manufacturer_Part_Number=313102S111116;313102S111116, Manufacturer=SAMTEC, Manufacturer_Part_Number=TSW-102-07-G-S
JP2 JP3: library part MCD-00214, "Header, 2x1, 2,54mm, VR, TH, Height 5.84mm/10.16mm", Manufacturer=SAMTEC, Manufacturer_Part_Number=TSW-102-09-G-S
JP5: library part MCD-00686, "Header, 4x2, 2,54mm, VR, TH, Height 5.84mm/2.54mm - Shunt Fitted 1-2", Manufacturer=SAMTEC, Manufacturer_Part_Number=TSW-104-07-G-D
JP6: library part MCD-00683, "Header, 2x1, 2,54mm, VR, TH, Height 5.84mm/2.54mm - Shunt Fitted by default", Alternate_Manufacturer=LIANYI, Alternate_Manufacturer_Part_Number=313102S111116, Manufacturer=SAMTEC, Manufacturer_Part_Number=TSW-102-07-G-S
L1: library part MCD-00047, "SMD Chip ferrite bead, 600R@100MHz +/-25%, 350mA, 500mohm DC, 0603, T=0.8mm", Manufacturer=TAI-TECH, Manufacturer_Part_Number=FCM1608KF-601T03
LD1: library part MCD-00051, "LED Bicolor", Alternate_Manufacturer=EVERLUCK, Alternate_Manufacturer_Part_Number=LE-RGW35280, Manufacturer="AVAGO TECHNOLOGIES", Manufacturer_Part_Number=HSMF-A201-A00J1
LD2: library part MCD-00049, "LED, Red, 0603", Alternate_Manufacturer="OSRAM OPTO SEMICONDUCTORS", Alternate_Manufacturer_Part_Number="LS Q976-NR-1", Manufacturer=EVERLIGHT, Manufacturer_Part_Number=19-213-R6C-AP1Q2B/3T, Package="LED 0603"
LD3 LD4: library part MCD-00050, "LED, Green, 0603", Alternate_Manufacturer="OSRAM OPTO SEMICONDUCTORS", Alternate_Manufacturer_Part_Number="LG Q396-PS-35", Manufacturer=EVERLIGHT, Manufacturer_Part_Number=19-213SYGC/S530-E2/TR8, Package="LED 0603"
R1 R3 R4 R14: library part MCD-00220, "Resistor,10K,0603,1%,1/10W", Alternate_Manufacturer=YAGEO, Alternate_Manufacturer_Part_Number=RT0402FRE07100KL, Manufacturer_Part_Number=RC0603FR-0710KL, Package=R0603
R2 R15 R18 R19 R20: library part MCD-00066, "Resistor,22R,0603,1%,1/10W", Alternate_Manufacturer=YAGEO, Alternate_Manufacturer_Part_Number=RT0402FRE07100KL, Manufacturer_Part_Number=RC0603FR-0722RL, Package=R0603
R5 R13: library part MCD-00223, "Resistor,100K,0603,1%,1/10W", Alternate_Manufacturer=YAGEO, Alternate_Manufacturer_Part_Number=RT0402FRE07100KL, Manufacturer_Part_Number=RC0603FR-07100KL, Package=R0603
R6 R23 R24 R29: library part MCD-00219, "Resistor,4K7,0603,1%,1/10W", Alternate_Manufacturer=YAGEO, Alternate_Manufacturer_Part_Number=RT0402FRE07100KL, Manufacturer_Part_Number=RC0603FR-074K7L, Package=R0603
R7: library part MCD-00218, "Resistor,2K7,0603,1%,1/10W", Alternate_Manufacturer=YAGEO, Alternate_Manufacturer_Part_Number=RT0402FRE07100KL, Manufacturer_Part_Number=RC0603FR-072K7L, Package=R0603
R8: library part MCD-00217, "Resistor,1K5,0603,1%,1/10W", Alternate_Manufacturer=YAGEO, Alternate_Manufacturer_Part_Number=RT0402FRE07100KL, Manufacturer_Part_Number=RC0603FR-071K5L, Package=R0603
R9: library part MCD-00221, "Resistor,36K,0603,1%,1/10W", Alternate_Manufacturer=YAGEO, Alternate_Manufacturer_Part_Number=RT0402FRE07100KL, Manufacturer_Part_Number=RC0603FR-0736KL, Package=R0603
R10 R21 R25 R26: library part MCD-00224, "Resistor,100R,0603,1%,1/10W", Alternate_Manufacturer=YAGEO, Alternate_Manufacturer_Part_Number=RT0402FRE07100KL, Manufacturer_Part_Number=RC0603FR-07100RL, Package=R0603
R11 R12: library part MCD-00197, "Resistor,330R,0603,1%,1/10W", Alternate_Manufacturer=YAGEO, Alternate_Manufacturer_Part_Number=RT0402FRE07100KL, Manufacturer_Part_Number=RC0603FR-07330RL, Package=R0603
R16 R28 R30: library part MCD-00070, "Resistor,1K,0603,1%,1/10W", Alternate_Manufacturer=YAGEO, Alternate_Manufacturer_Part_Number=RT0402FRE07100KL, Manufacturer_Part_Number=RC0603FR-071KL, Package=R0603
R17 R22: library part MCD-00222, "Resistor,47K,0603,1%,1/10W", Alternate_Manufacturer=YAGEO, Alternate_Manufacturer_Part_Number=RT0402FRE07100KL, Manufacturer_Part_Number=RC0603FR-0747KL, Package=R0603
R27: library part MCD-00225, "Resistor,510R,0603,1%,1/10W", Alternate_Manufacturer=YAGEO, Alternate_Manufacturer_Part_Number=RT0402FRE07100KL, Manufacturer_Part_Number=RC0603FR-07510RL, Package=R0603
R31 R32 R33 R34: library part MCD-00052, "Resistor,0R,0402,5%,1/16W", Alternate_Manufacturer=YAGEO, Alternate_Manufacturer_Part_Number=RT0402FRE07100KL, Manufacturer_Part_Number=RC0402JR-070RL, Package=R0402
R35: library part MCD-00257, "Resistor,1M,0603,1%,1/10W", Alternate_Manufacturer=YAGEO, Alternate_Manufacturer_Part_Number=RT0402FRE07100KL, Manufacturer_Part_Number=RC0603FR-071ML, Package=R0603
SB1 SB3 SB4 SB7 SB10 SB12 SB14 SB16 SB18 SB20 SB25 SB29 SB31 SB33: library part MCD-00072, "Solder Bridge OFF", Manufacturer=YAGEO, Manufacturer_Part_Number=RC0603JR-070RL, Package=SB0603
SB2 SB5 SB6 SB8 SB9 SB11 SB13 SB15 SB17 SB19 SB21 SB22 SB23 SB24 SB26 SB27 SB28 SB30 SB32: library part MCD-00071, "Solder Bridge ON", Manufacturer=YAGEO, Manufacturer_Part_Number=RC0603JR-070RL, Package=SB0603
T1: library part MCD-00073, "NPN Bipolar Transistor", Alternate_Manufacturer="ON SEMICONDUCTOR", Alternate_Manufacturer_Part_Number="MMBT2222LT1G / MMBT2222ALT1G / MMBT2222ALT3G", Manufacturer_Part_Number=BSR14, Package=SOT23
T2: library part MCD-01969, "Transistor, N-channel enhancement mode field-effect transistor", Alternate_Manufacturer=N/A, Manufacturer=NEXPERIA, Manufacturer_Part_Number=BSN20BK
U1: library part MCD-00163, "Very low capacitance ESD protection", Manufacturer=STMICROELECTRONICS
U2: library part MCD-00085, "Medium-density performance line ARM-based 32-bit MCU with 128KB Flash", Manufacturer=STMICROELECTRONICS
U3: library part MCD-00083, "Enhanced single channel power switches with active low enable pin", Alternate_Manufacturer="TEXAS INSTRUMENTS", Alternate_Manufacturer_Part_Number=TPS2041C, Manufacturer=STMICROELECTRONICS
U4: library part MCD-00663, "200 mA low quiescent current very low noise LDO", Manufacturer=STMICROELECTRONICS, Package=SOT23-5L
U5: library part MCD-00088, "IC REG LDO 5V 0.8A SOT223", Manufacturer=STMICROELECTRONICS, Package=SOT-223
U6: library part MCD-00664, "1.2 A low quiescent current LDO with reverse current protection", Manufacturer=STMICROELECTRONICS, Package=DFN6
U7: library part MCD-02301, "MCU, ARM™-based 32-bit MCU Cortex-M0+, 32KB Flash, 6KB SRAM", Alternate_Manufacturer=N/A, Manufacturer=STMICROELECTRONICS, Package=LQFP48
X1: library part MCD-00092, "Crystal 8MHz, 8pF, +-20ppm, 500ohms max,  SMD", Manufacturer=NDK, Manufacturer_Part_Number="NX3225GD 8MHz EXS00A-CG04874", Package=NX2012SA
X2: library part MCD-01479, "Crystal 32.768kHz, 6pF, -+20ppm, 80Kohm max, SMD", Manufacturer=NDK, Manufacturer_Part_Number="NX2012SA 32.768KHz EXS00A-MU00527", Package=NX2012SA
X3: library part MCD-02262, "Crystal 48MHz, 7pF, +-20 ppm, 80ohm max, SMD", Alternate_Manufacturer=N/A, Manufacturer=NDK, Manufacturer_Part_Number=NX1612SA_48MHz_EXS00A-CS13734, Package=NX1612SA

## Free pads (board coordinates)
  round 125.98 hole 125.98 unplated: 0(0,1950) 0(1300,-100) 0(1900,1900)
  round 20 on Mech16: 1(-121.22,-1004.31) 1(1801.9,-1004.31)

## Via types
v1: diameter 15, hole 8, Top Layer to Bottom Layer, tented both sides, 383 vias
v2: diameter 25, hole 12, Top Layer to Bottom Layer, tented both sides, 19 vias
v3: diameter 15, hole 8, Top Layer to Bottom Layer, 15 vias

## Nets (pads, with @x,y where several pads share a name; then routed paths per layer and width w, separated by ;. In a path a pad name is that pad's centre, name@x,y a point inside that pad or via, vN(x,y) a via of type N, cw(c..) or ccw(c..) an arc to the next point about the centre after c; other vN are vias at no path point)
3V3: CN6.2 CN6.4 CN7.12 CN7.16 JP6.2 R23.1 R27.2 SB2.2 | length 4816.3
  Top Layer w10: v1(726.43,2143.44) R23.1@774,2143.44 ; v1(745,1550) 925,1550 975,1500 JP6.2@975,1475 1151,1475 1189,1437 v1(1413,1437) ; v1(1757,1787) R27.2@1757,1813.74
  Top Layer w20: CN7.16@-200,1100 CN6.4@0,1100 43,1100 79,1136 79,1270 49,1300 CN6.2@0,1300 CN7.12@-200,1300 ; v2(375,1275) 385,1285 766.87,1285 767.37,1284.5 794.5,1284.5 855.06,1345.06 975,1345.06 ; JP6.2@975,1475 975,1345.06 ; 1105,1333.25 1109,1333.25 ; SB2.2@1105,1345.06 975,1345.06
  Bottom Layer w10: v1(726.43,2143.44) 320.48,2143.44 262,2084.96 262,1918.04 381.04,1799 605,1799 745,1659 v1(745,1550) ; v1(1413,1437) 1414.5,1438.5 1586.5,1438.5 1645,1497 1645,1606.46 1757,1718.46 v1(1757,1787)
  Bottom Layer w20: CN6.4@0,1100 200,1100 v2(375,1275) ; CN6.2@0,1300 CN6.2@3,1297
3V3_STLK: C1.2 C3.2 C7.2 C8.2 C10.2 C15.2 LD1.4 SB1.1 SB12.2 T1.3 U2.1 U2.9 U2.24 U2.36 U2.48 U4.5 | length 4695.8
  Top Layer w10: C10.2@696.5,2320 v1(736,2320) 739,2323 739,2377 752.79,2390.79 U2.9@782.68,2390.79 ; v1(746,2999) 796.64,2948.36 796.64,2895.4 885.94,2806.09 ; U2.1@782.68,2548.27 782.68,2575.68 814.32,2607.32 U2.48@841.73,2607.32 842,2607.59 C1.2@842,2681.44 865.44,2681.44 875,2691 875,2795.15 885.94,2806.09 ; v1(941,2331) 941.68,2331.68 1057.32,2331.68 1085.62,2303.38 v1(1085.62,2272.68) U2.24@1058.27,2272.68 C15.2@1058.27,2204.23 ; SB1.1@965,2737.4 965,2816.76 ; U2.36@1117.32,2548.27 1117.32,2558.32 1134.68,2575.68 C3.2@1188.5,2575.68 ; C3.2@1192.44,2575.68 1192.44,2641.55 v1(1206.89,2656) 1206.89,2800.07 1190.2,2816.76 965,2816.76 ; T1.3@1781,2924.31 1858.53,2924.31 v2(1860,2925.78) ; v2@1865,2926.06 LD1.4@1921.47,2926.06 ; 885.94,2806.09 896.61,2816.76 965,2816.76
  Top Layer w16: U4.5@1689.28,2411.4 U4.5@1690.77,2409.91
  Top Layer w20: U4.5@1689.28,2411.4 C8.2@1818.09,2411.4 ; v1(1690.77,2377.77) U4.5@1690.77,2409.91 ; C8.2@1819.02,2411.5 v2(1819.02,2445.98)
  Bottom Layer w10: SB12.2@267.25,2950 267.25,2978.25 304,3015 730,3015 v1(746,2999) ; v1(736,2320) 747,2331 v1(941,2331) ; v1(1085.62,2272.68) 1085.62,2336.76 1132.86,2384 1444.36,2384 1487.68,2340.68 1653.68,2340.68 v1(1690.77,2377.77)
  Bottom Layer w20: v1(1206.89,2656) 1255.89,2607 1335,2607 1395,2547 1790.92,2547 1806,2531.92 ; v2(1819.02,2445.98) 1819.02,2518.91 1806,2531.92 ; v2(1860,2925.78) 1860,2589.92 1862,2587.92 1806,2531.92
5V: C21.2 C22.2 CN6.5 CN7.18 D1.1 JP5.2 JP5.4 JP5.6 JP5.8 R28.1 U6.1 U6.6 | length 5453.2
  Top Layer w10: D1.1@1159,2751.13 v1(1184.87,2751.13) ; JP5.2@1550,1500 1626,1576 R28.1@1626,1813.44 1653.44,1813.44 1665,1825 1665,1965 1680,1980 v1(1680,1997.5)
  Top Layer w20: CN7.18@-200,1000 CN6.5@0,1000 ; v2(400,1249) 803,1249 845.32,1291.32 1212.62,1291.32 1214.44,1289.5 1282.5,1289.5 1285,1292 ; JP5.8@1250,1500 JP5.6@1350,1500 JP5.4@1450,1500 JP5.2@1550,1500 1591,1459 1591,1366 1561.13,1336.13 C22.2@1506,1336.13 C21.2@1446,1336.13 1423.13,1336.13 1410.18,1323.18 U6.1@1386.18,1323.18 ; U6.6@1283.82,1326.28 1283.82,1293.18 1285,1292 ; U6.1@1386.18,1326.28 U6.1@1386.18,1323.18 ; 1285,1292 1375.4,1292 1386.18,1302.78 U6.1@1386.18,1323.18
  Bottom Layer w10: v1(1184.87,2751.13) 1184.87,2811.99 1206.52,2833.64 1582.64,2833.64 1704,2955 1937,2955 1984,2908 1984,2768 2176,2576 2176,2460 2235.42,2400.58 2235.42,2325.42 2139,2229 1779,2229 1655,2105 1655,2039 1680,2014 v1(1680,1997.5)
  Bottom Layer w20: CN6.5@0,1000 150,1000 315,1165 316,1165 v2(400,1249)
5V_USB_CHG: C2.2 C6.2 CN1.1 CN10.8 D3.1 JP5.7 R14.2 R16.2 R17.2 R22.2 U1.5 U3.5 | length 5371
  Top Layer w10: U1.5@1437,2679.72 v1(1437,2715.69) ; 1549,2685 1552.56,2681.44 C2.2@1625,2681.44 R14.2@1684,2681.44
  Top Layer w16: CN1.1@1476.18,2886 1476.18,2852.82 1485,2844
  Top Layer w20: D3.1@1426.87,2410 1426.87,2483.61 1549,2605.73 ; 1485,2844 1520.5,2808.5 1549,2780 1549,2685 1549,2605.73 ; v2(1840.67,2260) 1885,2304.33 1885,2385.87 1910.69,2411.56 C6.2@1968,2411.56 1968,2496.83 1926.92,2537.92 ; C6.2@1968,2411.31 U3.5@2042.6,2411.31 2042.6,2489.69 2058.35,2505.44 R16.2@2111,2505.44 ; v2(2165,2355) 2165.44,2355.44 R22.2@2210,2355.44 ; CN10.8@2200,1500 v2(2282,1582) ; R17.2@2232.64,2560.56 2232.64,2603.36 2217,2619 2008,2619 1926.92,2537.92 ; 1549,2605.73 1549,2604 1581,2572 1892.83,2572 1926.92,2537.92
  Bottom Layer w10: v1(1437,2715.69) v1(1549.59,2715.69)
  Bottom Layer w20: JP5.7@1250,1600 1250,1660 1335,1745 1532,1745 1586,1799 1586,1975 ; v2(2165,2355) 2070,2260 v2(1840.67,2260) 1625,2260 1586,2221 1586,1975 ; 1586,1975 1600.27,1960.73 1679.29,1960.73 1691.56,1973 1775,1973 1800,1998 2220.61,1998 2282,1936.61 ; 2282,1936.61 v2(2282,1582) 2283.5,1583.5 2283.5,1935.11 2282,1936.61
5V_USB_STLK: C14.2 JP5.1 U3.1 | length 1118.8
  Top Layer w20: JP5.1@1550,1600 1550.53,1600.53 1550.53,1665 1575,1689.47 1575,1915 1592.25,1932.25 1592.25,2009.43 1618,2035.18 1618,2085 1679.63,2146.63 1944,2146.63 1961,2163.63 1961,2233 1983.56,2255.56 C14.2@2043,2255.56 2043,2324.29 U3.1@2042.6,2324.69
AGND: C29.1 C31.1 CN5.7 CN10.9 CN10.32 SB28.2 | length 3137.9
  Top Layer w20: CN5.7@1900,1460 2040,1460 CN10.9@2100,1400
  Bottom Layer w10: C31.1@672.44,825 722.44,875 SB28.2@723.62,875 730,875 730.5,874.5 870.05,874.5 1320.55,1325 1534.76,1325 1617.2,1407.44 1617.2,1440.2 1666,1489 1666,1531 1694.5,1559.5 C29.1@1719,1559.5 1719,1534 1743,1510 1769,1510 1819,1460 CN5.7@1900,1460 CN5.7@1905.5,1454.5 ; CN10.9@2100,1400 2150,1350 2240,1350 2260,1330 2260,310 2250,300 CN10.32@2200,300
AIN_1: R2.2 R23.2 R24.2 U2.10 | length 1407.3
  Top Layer w10: v1(27.44,2793.56) R2.2@27.44,2830 ; R23.2@774,2198.56 R24.2@834,2198.56 ; R23.2@774,2202.5 v1(774,2240) ; U2.10@782.68,2371.1 783.46,2370.32 811.68,2370.32 820,2362.01 v1(820,2295)
  Bottom Layer w10: v1(27.44,2793.56) 99.44,2793.56 181,2712 181,2531 244,2468 324,2468 552,2240 v1(774,2240) 790,2240 820,2270 v1(820,2295)
AVDD: C29.2 C31.2 SB25.2 SB30.1 U7.5 | length 1681.5
  Top Layer w10: U7.5@782.68,799.53 825.67,799.53 831.15,805 v1(832.5,805) ; v1(1460,1300) 1600,1300 1719,1419 v1(1719,1643)
  Bottom Layer w10: SB30.1@719.68,775 719.68,782.87 731.5,794.69 731.5,821.06 C31.2@727.56,825 835,825 ; v1(832.5,805) 832.5,822.5 835,825 ; v1(1460,1300) 1321.01,1300 846.01,825 835,825 ; v1(1719,1643) C29.2@1719,1614.62 1719.06,1614.69 SB25.2@1781,1614.69
E5V: CN7.6 D4.1 JP5.5 | length 2454.8
  Top Layer w20: CN7.6@-200,1600 -75,1600 25,1700 1000,1700 1050,1750 v2(1200,1750) ; v2@1199,1681.84 1268.16,1681.84 JP5.5@1350,1600 ; v2(1334.45,2209.45) 1334.45,2284.41 1384.04,2334 D4.1@1426.87,2334
  Bottom Layer w20: v2(1199,1681.46) 1199,2135 1273.45,2209.45 v2(1334.45,2209.45)
GND: B1.1 B1.2 B2.1 B2.2 C1.1 C2.1 C3.1 C4.1 C5.1 C6.1 C7.1 C8.1 C9.2 C10.1 C11.1 C12.1 C13.1 C14.1 C15.1 C17.1 C18.1 C19.1 C20.1 C21.1 C22.1 C23.1 C24.1 C25.1 C26.1 C27.2 C28.1 C32.1 C33.1 CN1.5 CN1.6 CN1.7 CN1.8 CN1.9 CN1.10 CN1.11 CN3.3 CN6.6 CN6.7 CN7.8 CN7.19 CN7.20 CN7.22 CN10.20 JP1.2 JP2.1 JP2.2 JP3.1 JP3.2 LD1.1 LD3.2 R1.2 R3.1 R4.1 R5.1 R6.2 R9.1 R13.2 R24.1 R26.1 R35.2 SB16.2 SB28.1 T2.2 U1.2 U2.8 U2.20 U2.23 U2.35 U2.47 U3.2 U4.2 U5.1 U6.2 U6.EP U7.7 X3.2 X3.4 | length 3254.3
  Top Layer w10: R1.2@86.5,2890 v1(125,2890) ; v1(210,1535) 210,1567.54 212,1569.54 C17.1@210,1571.54 ; v1(291,1390) U5.1@337,1390 ; R26.1@345,1987.56 v1(345,2019) ; v1(395,655) 397.28,657.28 C25.1@425,657.28 447.72,657.28 450.67,654.33 X3.2@485.24,654.33 ; v1(410,900) C23.1@432.28,900 ; v1(435,2421) C5.1@477.44,2421 C5.1@485.32,2421 ; v1(435,2496) C4.1@477.44,2496 C4.1@485.32,2496 ; B1.1@437.99,1988.58 v1(499.58,1988.58) ; X3.4@514.76,695.67 554.33,695.67 v1(575,675) ; v1(595,2320) C10.1@633.5,2320 ; C18.1@650,1458.46 v1(650,1505) ; v1(672.44,642.56) v1(672.44,577.56) v1@675,575 ; R3.1@720,2740.5 v1(720,2779) ; v1(737.53,2410.47) U2.8@782.68,2410.47 ; v1(750.42,1988.58) B1.2@812.01,1988.58 ; R4.1@780,2740.5 v1(780,2779) ; U7.7@782.68,760.16 829.84,760.16 v1(835,755) ; v1(834,2115) R24.1@834,2143.44 ; C1.1@840,2740.5 v1(840,2779) ; U2.47@861.42,2607.32 861.42,2575.04 862.23,2574.22 862.23,2573.57 871.8,2564 v1(881.63,2564) ; R5.1@911,2736.56 911,2770 v1(920,2779) ; v1(979.53,2234.17) U2.20@979.53,2272.68 ; R6.2@1020,2736.56 1020,2761.53 1037.47,2779 v1(1080,2779) ; U2.23@1038.58,2272.68 v1(1038.58,2311.18) ; v1(1060,2104) C15.1@1060,2139.5 ; B2.2@1104.72,1811.42 v1(1104.72,1865.28) ; U2.35@1117.32,2528.58 v1(1157.12,2528.58) ; C9.2@1192.44,2351 1192.44,2290 v1(1224.87,2257.56) ; v1(1225,1315) C20.1@1225,1341.13 ; C3.1@1251.5,2575.68 v1(1292,2575.68) ; v1(1270,2639) R13.2@1270,2677.5 ; CN1.7@1326.57,2886 CN1.5@1373.82,2886 ; v1(1335,1363.69) U6.2@1386.18,1363.69 1418.44,1363.69 C21.1@1446,1391.24 v1(1446,1418) ; v1@1419,2730 v1(1419,2731) 1437,2749 U1.2@1437,2770.28 U1.2@1437,2772.24 ; B2.1@1462.01,1811.42 v1(1462.01,1856.99) ; C22.1@1506,1391.24 v1(1506,1418) ; U4.2@1598.73,2374 U4.2@1600.7,2374 v1(1646,2374) ; LD3.2@1622.77,1983 LD3.2@1626,1986.23 v1(1657,1986.23) ; C2.1@1625,2740.5 v1(1625,2780) ; v1(1688.87,2172.13) C13.1@1688.87,2202.38 ; v1(1744,2638) R9.1@1744,2677.5 ; v1(1759.02,2328.45) C7.1@1759.02,2356.38 ; v1(1819.02,2328.61) C8.1@1819.02,2356.38 ; v2(1966.98,2330.02) C6.1@1966.98,2356.44 ; LD1.1@1979.53,2926.05 v1(2029.94,2926.05) ; v2(2043,2172) C14.1@2043,2200.44 ; U3.2@2080,2324.69 2080,2286.88 2096.1,2270.78 2128,2270.78 v2(2128,2271)
  Top Layer w20: CN7.22@-200,800 CN6.7@0,800 ; CN7.20@-200,900 CN6.6@0,900 ; C19.1@1165,1341.13 C20.1@1225,1341.13
  Bottom Layer w10: v1(229.54,2750) SB16.2@267.25,2750 ; v1(575,675) C33.1@672.44,675 ; v1(672.44,642.56) C33.1@672.44,675 ; C32.1@672.44,725 C33.1@672.44,675 ; 672.44,875 672.44,897.44 690,915 v1(690,922.5) ; v1(884,2453) 896.56,2465.56 C27.2@896.56,2491 ; v1(1652.27,1432) 1697.45,1477.18 R35.2@1718,1477.18 ; v1(1663,1276) 1681,1294 T2.2@1713,1294
  other v1: 1393,-177 117.82,-173 246.16,-173 374.49,-173 502.83,-173 631.17,-173 759.5,-173 887.84,-173 1016.17,-173 1144.51,-173 1251,-171.34 1537.02,-99 1783.24,-96.61 2008.24,-96.61 -366,-90 -237.66,-90 -109.33,-90 19.01,-90 147.34,-90 2309,-1.36 -409,24.64 660,35 1000,35 1710,35 1460,40 2309,126.97 2000,130 70,135 -409,152.97 175,205 640,220 835,225 2309,255.31 -409,281.31 1305,335 1510,340 1995,350 2309,383.64 -409,409.64 205,455 700,485 2309,511.98 250,520 70,535 -409,537.98 165,540 770,545 1090,575 310,595 395,595 153.07,601.85 -120,605 2309,640.32 1065,650 -409,666.32 1970,675 2035,675 1020,700 210,705 1065,740 403.24,743.39 2309,768.65 60,770 -409,794.65 345,805 1373.24,808.39 928.24,828.39 1773.24,838.39 1513.24,868.39 2309,896.99 1843.24,898.39 1123.24,908.39 1228.24,908.39 -409,922.99 365,965 750,970 815,970 423.24,1003.39 750,1025 815,1025 2309,1025.32 1133.24,1048.39 -409,1051.32 495,1055 335,1085 1733.24,1088.39 1218.24,1138.39 1638.24,1143.39 2309,1153.66 -409,1179.66 985,1205 855,1245 985,1255 1075,1260 1798.24,1268.39 -130,1270 -60,1270 2309,1281.99 -409,1307.99 100,1325 760,1370 1993.24,1408.39 2309,1410.33 1557.72,1413.41 -409,1436.33 1190,1465 1395,1465 1050,1500 1998.24,1513.39 1803.24,1523.39 -40,1525 2309,1538.66 -409,1564.66 590,1630 -95,1635 990,1640 2003.24,1653.39 2309,1667 1783.24,1673.39 2254,1680 -409,1693 25,1730 190,1730 385,1730 570,1730 725,1735 910,1735 2003.24,1758.39 1835,1770 321,1772 2309,1795.34 -409,1821.34 1238,1824 2250,1842 391,1871.5 206,1890 2309,1895.34 -409,1921.34 1500,1935 1715,1938 1997.92,1958 2193,1960.98 1809,1964 2303,2000 1243.5,2015 205,2017 69.65,2019 1400,2020 -407,2021.34 -303,2021.34 -203,2021.34 -103,2021.34 1703,2025 1835.91,2025 1965.49,2027 2095,2027 1231.77,2105.53 2281,2107 1707.57,2108.68 1835.91,2108.68 1964.25,2108.68 2092.58,2108.68 1548.04,2112.53 1410.18,2115 -385.34,2117 -257.01,2117 -128.67,2117 -0.34,2117 128,2117 1197.54,2174.53 1880,2193.87 2263.45,2204 1465,2210.8 1466.29,2294.48 -388.43,2358.34 2281,2403.99 1334,2431 1858.15,2435.09 1786.97,2442.95 2015,2445.25 -1.77,2447 2221,2465 2131.68,2465.65 1067.77,2482.53 1215.04,2485.28 -388.43,2486.67 1380,2488.13 1486.72,2494.15 1858.73,2514.53 -385.43,2524.01 2281,2532.33 687.77,2552.53 2017,2560.56 352.87,2562 525.77,2562.43 -8.43,2567.95 1470.03,2575.68 1405,2587 1582.21,2648.53 -385.43,2652.34 36.87,2652.94 2281,2660.66 1516.28,2672.07 282,2695.74 515.26,2724 1365,2767.57 1232,2778.17 1703.77,2778.53 1776.51,2778.53 -385.43,2780.68 1512,2780.68 2281,2789 274,2795 1008.94,2854.34 1641.29,2857 1950,2865 -385.43,2880.68 2281,2889 1734.77,2890.53 918.64,2911.2 1182.62,2911.2 716.77,2925.53 -385.43,2980.68 1040.32,2982.75 919.35,2985 317.99,2987.62 2281,2989 685.8,2990 -307.34,3003 -179.01,3003 -50.67,3003 77.66,3003 206,3003 1652.66,3016 1780.99,3016 1909.33,3016 2037.66,3016 2166,3016 861.66,3019 1375,3019 1232,3020 991,3030 1118,3030
LED_STLK: R11.1 R12.1 U2.30 | length 1176.4
  Top Layer w10: v1(1386.32,2452) 1178.7,2452 1156.85,2430.16 1143.63,2430.16 ; v1(1921,2637) R11.1@1921,2677.5 ; R11.1@1921,2681.44 R12.1@1980,2681.44 ; 1143.63,2430.16 U2.30@1117.32,2430.16 1143.63,2430.16
  Bottom Layer w10: v1(1386.32,2452) 1726,2452 1775,2403 1893,2403 1921,2431 v1(1921,2637)
MCO: SB20.2 SB29.2 | length 1892.3
  Top Layer w8: v1(570,805) SB29.2@601.38,805
  Bottom Layer w8: v1(570,805) 570,835 735,1000 885,1000 1168,1283 1168,2186 1195.5,2213.5 SB20.2@1195.5,2315.72
  Bottom Layer w10: SB20.2@1193.22,2318 SB20.2@1195.5,2315.72
NetB1_3: B1.3 B1.4 C16.2 R29.1 SB24.2 | length 683
  Top Layer w10: R29.1@290,1808.5 B1.3@451.81,1808.5 ; B1.3@454.72,1811.42 B1.4@812.01,1811.42 878.42,1811.42 897.88,1830.88 v1(897.88,1864.62)
  Bottom Layer w10: v1(897.88,1864.62) SB24.2@934.11,1864.62
NetC9_1: C9.1 R21.2 SB20.1 | length 155.6
  Top Layer w10: R21.2@1247.56,2411 C9.1@1247.56,2351 1255.56,2359 v1(1277.48,2359)
  Bottom Layer w10: 1246.09,2321 1246.09,2347.09 1258,2359 v1(1277.48,2359)
NetC11_2: C11.2 C12.2 D3.2 D4.2 D5.2 U4.1 U4.3 | length 436.5
  Top Layer w16: U4.3@1596.13,2334 U4.3@1598.73,2336.6 ; U4.3@1600.7,2336.6 U4.3@1601,2336.3 ; C12.2@1629.31,2257 C12.2@1629.87,2257.56
  Top Layer w20: D3.2@1511.13,2410 D4.2@1511.13,2334 D5.2@1511.13,2257 1601,2257 ; D3.2@1516.24,2410 U4.1@1597.33,2410 ; U4.3@1601,2336.3 1601,2257 ; C12.2@1629.31,2257 1601,2257
NetC13_2: C13.2 U4.4 | length 75.2
  Top Layer w20: C13.2@1689.28,2261.43 U4.4@1689.28,2336.6
NetC16_1: C16.1 R26.2 | length 57
  Top Layer w10: C16.1@345,1871.5 R26.2@345,1928.5
NetC19_2: C19.2 C20.2 SB2.1 U6.4 | length 183.6
  Top Layer w20: 1102.24,1396.24 C19.2@1165,1396.24 C20.2@1225,1396.24 1257.24,1396.24 1262.09,1401.09 U6.4@1283.82,1401.09
NetC23_2: C23.2 R31.1 X2.2 | length 139.6
  Top Layer w8: C23.2@467.72,900 R31.1@607.28,900
NetC24_2: C24.2 R32.1 X2.1 | length 139.6
  Top Layer w8: C24.2@467.72,850 R32.1@607.28,850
